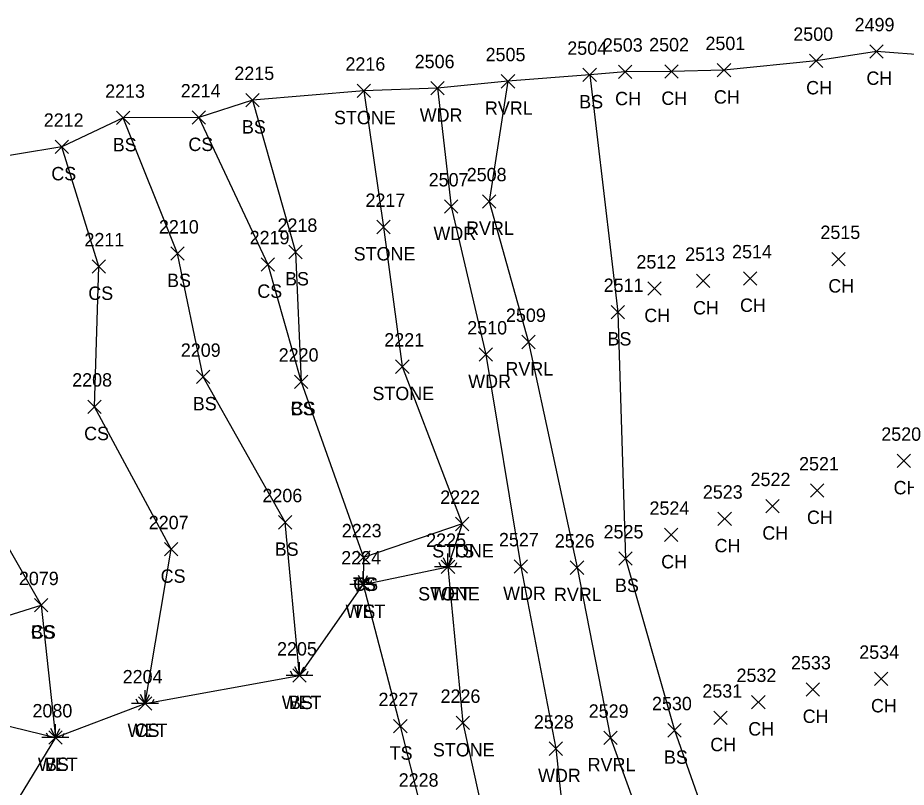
# Model space of a CAD drawing. Extents: x 1512665 to 1513714, y 110636 to 112816.
# Drawn here: x 1512914.5 to 1513047.2, y 110982.6 to 111097.6 of the extents above; entities that cross this region are included whole.
import ezdxf

# ---------------------------------------------------------------- set-up
doc = ezdxf.new("R2010")
doc.units = 0
for name, color, linetype in [('L_A', 7, 'Continuous'), ('L_I', 7, 'Continuous'), ('L_TIC', 7, 'Continuous'), ('LASF', 7, 'Continuous'), ('LAWA', 7, 'Continuous'), ('LAWE', 7, 'Continuous'), ('LELB', 7, 'Continuous'), ('LSOGP', 7, 'Continuous'), ('LWET', 7, 'Continuous')]:
    doc.layers.add(name, color=color, linetype=linetype)

msp = doc.modelspace()

# ---------------------------------------------------------------- linework, layer by layer
at = {"layer": 'L_TIC'}
for points in [[(1513041.76, 111091.55), (1513043.76, 111093.55)], [(1513043.76, 111091.55), (1513041.76, 111093.55)], [(1513032.76, 111090.13), (1513034.76, 111092.13)], [(1513034.76, 111090.13), (1513032.76, 111092.13)], [(1512998.92, 111088.04), (1513000.92, 111090.04)], [(1513000.92, 111088.04), (1512998.92, 111090.04)], [(1513004.23, 111088.51), (1513006.23, 111090.51)], [(1513006.23, 111088.51), (1513004.23, 111090.51)], [(1513011.14, 111088.56), (1513013.14, 111090.56)], [(1513013.14, 111088.56), (1513011.14, 111090.56)], [(1513018.98, 111088.75), (1513020.98, 111090.75)], [(1513020.98, 111088.75), (1513018.98, 111090.75)], [(1512986.72, 111087.08), (1512988.72, 111089.08)], [(1512988.72, 111087.08), (1512986.72, 111089.08)], [(1512965.2, 111085.67), (1512967.2, 111087.67)], [(1512967.2, 111085.67), (1512965.2, 111087.67)], [(1512976.18, 111086.04), (1512978.18, 111088.04)], [(1512978.18, 111086.04), (1512976.18, 111088.04)], [(1512948.55, 111084.28), (1512950.55, 111086.28)], [(1512950.55, 111084.28), (1512948.55, 111086.28)], [(1512929.26, 111081.62), (1512931.26, 111083.62)], [(1512931.26, 111081.62), (1512929.26, 111083.62)], [(1512940.55, 111081.67), (1512942.55, 111083.67)], [(1512942.55, 111081.67), (1512940.55, 111083.67)], [(1512920.08, 111077.29), (1512922.08, 111079.29)], [(1512922.08, 111077.29), (1512920.08, 111079.29)], [(1512983.9, 111069.15), (1512985.9, 111071.15)], [(1512985.9, 111069.15), (1512983.9, 111071.15)], [(1512978.22, 111068.38), (1512980.22, 111070.38)], [(1512980.22, 111068.38), (1512978.22, 111070.38)], [(1512968.13, 111065.32), (1512970.13, 111067.32)], [(1512970.13, 111065.32), (1512968.13, 111067.32)], [(1512937.37, 111061.35), (1512939.37, 111063.35)], [(1512939.37, 111061.35), (1512937.37, 111063.35)], [(1512954.99, 111061.59), (1512956.99, 111063.59)], [(1512956.99, 111061.59), (1512954.99, 111063.59)], [(1512950.84, 111059.74), (1512952.84, 111061.74)], [(1512952.84, 111059.74), (1512950.84, 111061.74)], [(1513036.07, 111060.53), (1513038.07, 111062.53)], [(1513038.07, 111060.53), (1513036.07, 111062.53)], [(1512925.6, 111059.43), (1512927.6, 111061.43)], [(1512927.6, 111059.43), (1512925.6, 111061.43)], [(1513015.87, 111057.26), (1513017.87, 111059.26)], [(1513017.87, 111057.26), (1513015.87, 111059.26)], [(1513022.88, 111057.64), (1513024.88, 111059.64)], [(1513024.88, 111057.64), (1513022.88, 111059.64)], [(1513008.59, 111056.12), (1513010.59, 111058.12)], [(1513010.59, 111056.12), (1513008.59, 111058.12)], [(1513003.14, 111052.62), (1513005.14, 111054.62)], [(1513005.14, 111052.62), (1513003.14, 111054.62)], [(1512989.77, 111048.14), (1512991.77, 111050.14)], [(1512991.77, 111048.14), (1512989.77, 111050.14)], [(1512983.42, 111046.27), (1512985.42, 111048.27)], [(1512985.42, 111046.27), (1512983.42, 111048.27)], [(1512970.94, 111044.46), (1512972.94, 111046.46)], [(1512972.94, 111044.46), (1512970.94, 111046.46)], [(1512941.21, 111042.93), (1512943.21, 111044.93)], [(1512943.21, 111042.93), (1512941.21, 111044.93)], [(1512955.83, 111042.21), (1512957.83, 111044.21)], [(1512957.83, 111042.21), (1512955.83, 111044.21)], [(1512955.83, 111042.21), (1512957.83, 111044.21)], [(1512957.83, 111042.21), (1512955.83, 111044.21)], [(1512924.98, 111038.48), (1512926.98, 111040.48)], [(1512926.98, 111038.48), (1512924.98, 111040.48)], [(1513045.82, 111030.39), (1513047.82, 111032.39)], [(1513047.82, 111030.39), (1513045.82, 111032.39)], [(1513032.88, 111025.96), (1513034.88, 111027.96)], [(1513034.88, 111025.96), (1513032.88, 111027.96)], [(1513026.21, 111023.62), (1513028.21, 111025.62)], [(1513028.21, 111023.62), (1513026.21, 111025.62)], [(1512953.45, 111021.21), (1512955.45, 111023.21)], [(1512955.45, 111021.21), (1512953.45, 111023.21)], [(1513019.08, 111021.74), (1513021.08, 111023.74)], [(1513021.08, 111021.74), (1513019.08, 111023.74)], [(1512979.86, 111020.96), (1512981.86, 111022.96)], [(1512981.86, 111020.96), (1512979.86, 111022.96)], [(1512979.86, 111020.96), (1512981.86, 111022.96)], [(1512981.86, 111020.96), (1512979.86, 111022.96)], [(1513011.11, 111019.33), (1513013.11, 111021.33)], [(1513013.11, 111019.33), (1513011.11, 111021.33)], [(1512936.41, 111017.18), (1512938.41, 111019.18)], [(1512938.41, 111017.18), (1512936.41, 111019.18)], [(1512965.16, 111015.97), (1512967.16, 111017.97)], [(1512967.16, 111015.97), (1512965.16, 111017.97)], [(1512965.16, 111015.97), (1512967.16, 111017.97)], [(1512967.16, 111015.97), (1512965.16, 111017.97)], [(1512988.63, 111014.62), (1512990.63, 111016.62)], [(1512990.63, 111014.62), (1512988.63, 111016.62)], [(1513004.26, 111015.8), (1513006.26, 111017.8)], [(1513006.26, 111015.8), (1513004.26, 111017.8)], [(1512977.76, 111014.54), (1512979.76, 111016.54)], [(1512979.76, 111014.54), (1512977.76, 111016.54)], [(1512997.03, 111014.44), (1512999.03, 111016.44)], [(1512999.03, 111014.44), (1512997.03, 111016.44)], [(1512965.08, 111011.92), (1512967.08, 111013.92)], [(1512967.08, 111011.92), (1512965.08, 111013.92)], [(1512917.02, 111008.83), (1512919.02, 111010.83)], [(1512919.02, 111008.83), (1512917.02, 111010.83)], [(1512917.02, 111008.83), (1512919.02, 111010.83)], [(1512919.02, 111008.83), (1512917.02, 111010.83)], [(1512955.57, 110998.31), (1512957.57, 111000.31)], [(1512957.57, 110998.31), (1512955.57, 111000.31)], [(1513042.44, 110997.82), (1513044.44, 110999.82)], [(1513044.44, 110997.82), (1513042.44, 110999.82)], [(1513032.25, 110996.24), (1513034.25, 110998.24)], [(1513034.25, 110996.24), (1513032.25, 110998.24)], [(1512932.52, 110994.15), (1512934.52, 110996.15)], [(1512934.52, 110994.15), (1512932.52, 110996.15)], [(1513024.11, 110994.36), (1513026.11, 110996.36)], [(1513026.11, 110994.36), (1513024.11, 110996.36)], [(1513018.44, 110992.02), (1513020.44, 110994.02)], [(1513020.44, 110992.02), (1513018.44, 110994.02)], [(1512970.64, 110990.75), (1512972.64, 110992.75)], [(1512972.64, 110990.75), (1512970.64, 110992.75)], [(1512979.96, 110991.24), (1512981.96, 110993.24)], [(1512981.96, 110991.24), (1512979.96, 110993.24)], [(1513011.57, 110990.14), (1513013.57, 110992.14)], [(1513013.57, 110990.14), (1513011.57, 110992.14)], [(1512919.13, 110989.07), (1512921.13, 110991.07)], [(1512921.13, 110989.07), (1512919.13, 110991.07)], [(1513002.05, 110989.02), (1513004.05, 110991.02)], [(1513004.05, 110989.02), (1513002.05, 110991.02)], [(1512993.85, 110987.4), (1512995.85, 110989.4)], [(1512995.85, 110987.4), (1512993.85, 110989.4)]]:
    msp.add_lwpolyline(points, dxfattribs=at)
at = {"layer": 'LASF'}
msp.add_lwpolyline([(1512966.2, 111086.67), (1512969.13, 111066.32), (1512971.94, 111045.46), (1512980.86, 111021.96), (1512978.76, 111015.54), (1512980.96, 110992.24), (1512985.65, 110971.06), (1512992.38, 110959.14)], dxfattribs=at)
at = {"layer": 'LAWA'}
msp.add_lwpolyline([(1512977.18, 111087.04), (1512979.22, 111069.38), (1512984.42, 111047.27), (1512989.63, 111015.62), (1512994.85, 110988.4), (1512997.96, 110959.71), (1513004.77, 110944.17), (1513009.33, 110931.39), (1513020.98, 110918.63), (1513027.1, 110906.99), (1513030.6, 110898.71), (1513042.86, 110889.73), (1513042.54, 110875.66), (1513037.08, 110875.12), (1513033.74, 110859.16), (1513040, 110853.34)], dxfattribs=at)
at = {"layer": 'LAWE'}
msp.add_lwpolyline([(1512987.72, 111088.08), (1512984.9, 111070.15), (1512990.77, 111049.14), (1512998.03, 111015.44), (1513003.05, 110990.02), (1513012.42, 110964.07), (1513015.69, 110940.33), (1513022.51, 110936.75), (1513029.31, 110920.67), (1513038.86, 110910.1), (1513045.15, 110901.71)], dxfattribs=at)
at = {"layer": 'LELB'}
for points in [[(1512999.92, 111089.04), (1513004.14, 111053.62), (1513005.26, 111016.8), (1513012.57, 110991.14), (1513021.16, 110966.86), (1513021.14, 110942.53), (1513029.13, 110937.33), (1513035.68, 110924.63), (1513037.26, 110919.75), (1513042.36, 110913.68), (1513051.02, 110904.49)], [(1512949.55, 111085.28), (1512955.99, 111062.59), (1512956.83, 111043.21)], [(1512956.57, 110999.31), (1512954.45, 111022.21), (1512942.21, 111043.93), (1512938.37, 111062.35), (1512930.26, 111082.62)], [(1512941.55, 111082.67), (1512951.84, 111060.74), (1512956.83, 111043.21), (1512966.16, 111016.97)], [(1512933.52, 110995.15), (1512937.41, 111018.18), (1512925.98, 111039.48), (1512926.6, 111060.43), (1512921.08, 111078.29)], [(1512881, 111069.89), (1512889.28, 111054.32), (1512904.05, 111034.19), (1512918.02, 111009.83), (1512920.13, 110990.07), (1512909.26, 110972.23), (1512893.57, 110955.66)], [(1512852.64, 111040.52), (1512867.53, 111036.18), (1512870.18, 111035.72), (1512876.82, 111021.74), (1512897.45, 111003.41), (1512918.02, 111009.83)], [(1512980.86, 111021.96), (1512966.16, 111016.97), (1512966.08, 111012.92), (1512971.64, 110991.75), (1512974.66, 110979.72), (1512973.51, 110967.07), (1512980.17, 110961.83), (1512987.45, 110935), (1512995.77, 110918.8), (1513003.18, 110910.23), (1513008.97, 110899.99), (1513018.79, 110891.62), (1513028.51, 110881.74), (1513026.69, 110865.34), (1513034.96, 110851.42)]]:
    msp.add_lwpolyline(points, dxfattribs=at)
at = {"layer": 'LSOGP'}
msp.add_lwpolyline([(1513050.57, 111091.96), (1513042.76, 111092.55), (1513033.76, 111091.13), (1513019.98, 111089.75), (1513012.14, 111089.57), (1513005.24, 111089.51), (1512999.92, 111089.04), (1512987.72, 111088.08), (1512977.18, 111087.04), (1512966.2, 111086.68), (1512949.55, 111085.28), (1512941.54, 111082.68), (1512930.25, 111082.63), (1512921.08, 111078.29), (1512907.79, 111076.13)], dxfattribs=at)
at = {"layer": 'LWET'}
for p, q in [((1512978.76, 111015.54), (1512978.09, 111016.88)), ((1512978.76, 111015.54), (1512978.76, 111017.54)), ((1512978.76, 111015.54), (1512979.42, 111016.88)), ((1512980.76, 111015.54), (1512976.76, 111015.54)), ((1512977.76, 111015.54), (1512977.42, 111016.21)), ((1512979.76, 111015.54), (1512980.09, 111016.21)), ((1512966.08, 111012.92), (1512965.41, 111014.26)), ((1512966.08, 111012.92), (1512966.08, 111014.92)), ((1512966.08, 111012.92), (1512966.75, 111014.26)), ((1512968.08, 111012.92), (1512964.08, 111012.92)), ((1512965.08, 111012.92), (1512964.75, 111013.59)), ((1512967.08, 111012.92), (1512967.41, 111013.59)), ((1512956.57, 110999.31), (1512956.57, 111001.31)), ((1512955.57, 110999.31), (1512955.23, 110999.98)), ((1512956.57, 110999.31), (1512955.9, 111000.64)), ((1512956.57, 110999.31), (1512957.23, 111000.64)), ((1512957.57, 110999.31), (1512957.9, 110999.98)), ((1512958.57, 110999.31), (1512954.57, 110999.31)), ((1512933.52, 110995.15), (1512933.52, 110997.15)), ((1512932.52, 110995.15), (1512932.19, 110995.81)), ((1512933.52, 110995.15), (1512932.86, 110996.48)), ((1512933.52, 110995.15), (1512934.19, 110996.48)), ((1512934.52, 110995.15), (1512934.86, 110995.81)), ((1512935.52, 110995.15), (1512931.52, 110995.15)), ((1512920.13, 110990.07), (1512919.47, 110991.41)), ((1512920.13, 110990.07), (1512920.13, 110992.07)), ((1512920.13, 110990.07), (1512920.8, 110991.41)), ((1512922.13, 110990.07), (1512918.13, 110990.07)), ((1512919.13, 110990.07), (1512918.8, 110990.74)), ((1512921.13, 110990.07), (1512921.47, 110990.74))]:
    msp.add_line(p, q, dxfattribs=at)
msp.add_lwpolyline([(1512827.59, 110974.32), (1512838.97, 110985.23), (1512857.89, 110992.02), (1512872.08, 110997.37), (1512896.47, 110995.84), (1512920.13, 110990.07), (1512933.52, 110995.15), (1512956.57, 110999.31), (1512966.08, 111012.92), (1512978.76, 111015.54)], dxfattribs=at)

# ---------------------------------------------------------------- texts
at = {"layer": 'L_A'}
for s, p in [('CH', (1513041.25, 111087.55)), ('CH', (1513032.25, 111086.13)), ('BS', (1512998.36, 111084.04)), ('CH', (1513003.72, 111084.51)), ('CH', (1513010.62, 111084.56)), ('CH', (1513018.47, 111084.75)), ('RVRL', (1512984.28, 111083.08)), ('STONE', (1512961.74, 111081.67)), ('WDR', (1512974.54, 111082.04)), ('BS', (1512947.99, 111080.28)), ('BS', (1512928.7, 111077.62)), ('CS', (1512939.99, 111077.67)), ('CS', (1512919.52, 111073.29)), ('RVRL', (1512981.46, 111065.15)), ('WDR', (1512976.59, 111064.38)), ('STONE', (1512964.68, 111061.32)), ('BS', (1512936.81, 111057.35)), ('BS', (1512954.43, 111057.59)), ('CS', (1512950.28, 111055.74)), ('CH', (1513035.56, 111056.53)), ('CS', (1512925.04, 111055.43)), ('CH', (1513015.36, 111053.26)), ('CH', (1513022.37, 111053.64)), ('CH', (1513008.08, 111052.12)), ('BS', (1513002.58, 111048.62)), ('RVRL', (1512987.34, 111044.14)), ('WDR', (1512981.78, 111042.27)), ('STONE', (1512967.48, 111040.46)), ('BS', (1512940.65, 111038.93)), ('CS', (1512955.27, 111038.21)), ('BS', (1512955.27, 111038.21)), ('CS', (1512924.42, 111034.48)), ('CH', (1513045.31, 111026.39)), ('CH', (1513032.37, 111021.96)), ('CH', (1513025.7, 111019.62)), ('BS', (1512952.89, 111017.21)), ('CH', (1513018.57, 111017.74)), ('STONE', (1512976.4, 111016.96)), ('TS', (1512979.27, 111016.96)), ('CH', (1513010.6, 111015.33)), ('CS', (1512935.85, 111013.18)), ('TS', (1512964.57, 111011.97)), ('CS', (1512964.6, 111011.97)), ('WDR', (1512986.99, 111010.62)), ('BS', (1513003.7, 111011.8)), ('STONE', (1512974.3, 111010.54)), ('WET', (1512976.14, 111010.54)), ('RVRL', (1512994.59, 111010.44)), ('TS', (1512964.49, 111007.92)), ('WET', (1512963.46, 111007.92)), ('CS', (1512916.47, 111004.83)), ('BS', (1512916.47, 111004.83)), ('WET', (1512953.94, 110994.31)), ('BS', (1512955.01, 110994.31)), ('CH', (1513041.93, 110993.82)), ('CH', (1513031.73, 110992.24)), ('WET', (1512930.9, 110990.15)), ('CS', (1512931.96, 110990.15)), ('CH', (1513023.6, 110990.36)), ('CH', (1513017.93, 110988.02)), ('TS', (1512970.05, 110986.75)), ('STONE', (1512976.51, 110987.24)), ('BS', (1513011.01, 110986.14)), ('WET', (1512917.51, 110985.07)), ('BS', (1512918.57, 110985.07)), ('RVRL', (1512999.62, 110985.02)), ('WDR', (1512992.21, 110983.4))]:
    msp.add_text(s, height=2, dxfattribs=at).set_placement(p)
at = {"layer": 'L_I'}
for s, p in [('2499', (1513039.49, 111095.55)), ('2500', (1513030.33, 111094.13)), ('2504', (1512996.58, 111092.04)), ('2503', (1513001.89, 111092.51)), ('2502', (1513008.8, 111092.56)), ('2501', (1513017.21, 111092.75)), ('2505', (1512984.38, 111091.08)), ('2216', (1512963.45, 111089.67)), ('2506', (1512973.79, 111090.04)), ('2215', (1512946.86, 111088.28)), ('2213', (1512927.56, 111085.62)), ('2214', (1512938.85, 111085.67)), ('2212', (1512918.39, 111081.29)), ('2508', (1512981.56, 111073.15)), ('2507', (1512975.88, 111072.38)), ('2217', (1512966.44, 111069.32)), ('2210', (1512935.59, 111065.35)), ('2218', (1512953.3, 111065.59)), ('2219', (1512949.14, 111063.74)), ('2515', (1513034.38, 111064.53)), ('2211', (1512924.47, 111063.43)), ('2513', (1513014.18, 111061.26)), ('2514', (1513021.19, 111061.64)), ('2512', (1513006.9, 111060.12)), ('2511', (1513002.01, 111056.62)), ('2509', (1512987.42, 111052.14)), ('2510', (1512981.64, 111050.27)), ('2221', (1512969.25, 111048.46)), ('2209', (1512938.86, 111046.93)), ('2220', (1512953.48, 111046.21)), ('2220', (1512953.48, 111046.21)), ('2208', (1512922.64, 111042.48)), ('2520', (1513043.47, 111034.39)), ('2521', (1513031.19, 111029.96)), ('2522', (1513023.95, 111027.62)), ('2206', (1512951.05, 111025.21)), ('2523', (1513016.82, 111025.74)), ('2222', (1512977.6, 111024.96)), ('2222', (1512977.6, 111024.96)), ('2524', (1513008.85, 111023.33)), ('2207', (1512934.07, 111021.18)), ('2223', (1512962.9, 111019.97)), ('2223', (1512962.9, 111019.97)), ('2225', (1512975.5, 111018.54)), ('2225', (1512975.5, 111018.54)), ('2527', (1512986.37, 111018.62)), ('2525', (1513002, 111019.8)), ('2526', (1512994.71, 111018.44)), ('2224', (1512962.82, 111015.92)), ('2224', (1512962.82, 111015.92)), ('2079', (1512914.68, 111012.83)), ('2079', (1512914.68, 111012.83)), ('2205', (1512953.23, 111002.31)), ('2205', (1512953.23, 111002.31)), ('2534', (1513040.18, 111001.82)), ('2533', (1513029.99, 111000.24)), ('2204', (1512930.18, 110998.15)), ('2204', (1512930.18, 110998.15)), ('2532', (1513021.85, 110998.36)), ('2531', (1513016.75, 110996.02)), ('2227', (1512968.38, 110994.75)), ('2226', (1512977.65, 110995.24)), ('2530', (1513009.23, 110994.14)), ('2080', (1512916.71, 110993.07)), ('2080', (1512916.71, 110993.07)), ('2529', (1512999.78, 110993.02)), ('2528', (1512991.59, 110991.4)), ('2228', (1512971.4, 110982.72))]:
    msp.add_text(s, height=2, dxfattribs=at).set_placement(p)

doc.saveas('drawing.dxf')
